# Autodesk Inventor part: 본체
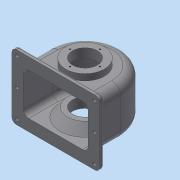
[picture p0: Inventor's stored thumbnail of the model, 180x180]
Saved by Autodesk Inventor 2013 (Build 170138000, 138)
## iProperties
Created: 2015-09
Part Number: 본체
Material: 일반
Document SubType Name: Modeling
Designer: Administrator
Density: 1 g/cm^3
Author: Administrator
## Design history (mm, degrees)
sketch "스케치1"
  geometry: L1 (0, 0)-(0, -47); L2 (0, -47)-(0, 57); L3 (0, -47)-(57, -47); L4 (57, -47)-(57, 0); L5 (0, -47)-(-57, -47); L6 (-57, -47)-(-57, 0); A1 r 57 centre (0, 0) between (57, 0) and (-57, 0)
  constraints: 12 end point, 3 point on circle, 2 perpendicular, 2 tangent, 1 centre point, 1 coincident, 1 collinear, 1 vertical
  dimensions: "d0" = 47 distance of L1.start L1.end; "d1" = 104 distance of L1.end L2.end
extrude "돌출1" new body sketch "스케치1" stored distance "d2" = 77; taper "d3" = 0 deg
fillet "모깎기1" dims "d4" = 14
feature "쉘2" dims "d16" = 5
sketch "스케치5"
  geometry: C1 r 31 at (0, 0); A1 r 43 centre (0, 0) between (43, 0) and (-43, 0) reference
  constraints: 1 centre point, 1 coincident
  dimensions: "d17" = 62 diameter of C1
extrude "돌출4" join sketch "스케치5" distance "d18" = 10; taper "d19" = 0 deg
sketch "스케치6"
  geometry: C1 r 31 at (0, 0) reference; C2 r 20 at (0, 0)
  constraints: 1 centre point, 1 coincident
  dimensions: "d20" = 40 diameter of C2
extrude "돌출5" cut sketch "스케치6" stored distance "d21" = 10; taper "d22" = 0 deg
sketch "스케치7"
  geometry: L1 (-31, 38.5)-(-31, 48.5) reference; L2 (-31, 48.5)-(-20, 48.5) reference; L3 (-20, 48.5)-(-20, 33.5) reference; L4 (-20, 33.5)-(-47, 33.5) reference; L5 (-47, 33.5)-(-47, 38.5) reference; L6 (-47, 38.5)-(-31, 38.5) reference; L7 (57, 24.5)-(57, -24.5) reference; L8 (43, -38.5)-(-47, -38.5) reference; L9 (-47, -38.5)-(-47, -33.5) reference; L10 (-47, -33.5)-(43, -33.5) reference; L11 (52, -24.5)-(52, 24.5) reference; L12 (43, 33.5)-(20, 33.5) reference; L13 (20, 33.5)-(20, 48.5) reference; L14 (20, 48.5)-(31, 48.5) reference; L15 (31, 48.5)-(31, 38.5) reference; L16 (31, 38.5)-(43, 38.5) reference; L17 (0, -19.5)-(28, -19.5); L18 (0, -33.5)-(39.747, -33.5); L19 (28, -19.5)-(39.747, -33.5); L20 (0, -33.5)-(0, -19.5); A1 r 14 centre (43, 24.5) between (57, 24.5) and (43, 38.5) reference; A2 r 14 centre (43, -24.5) between (43, -38.5) and (57, -24.5) reference; A3 r 9 centre (43, -24.5) between (43, -33.5) and (52, -24.5) reference; A4 r 9 centre (43, 24.5) between (52, 24.5) and (43, 33.5) reference; 1 further point
  constraints: 8 end point, 2 point on line, 1 perpendicular
  dimensions: "d24" = 28 distance of L17.start L17.end
revolve "회전1" sketch "스케치7" stored, may be unused: angle "d26" = 90 deg
sketch "스케치8"
  geometry: L1 (-31, 38.5)-(-31, 48.5) reference; L2 (-31, 48.5)-(-20, 48.5) reference; L3 (-20, 48.5)-(-20, 33.5) reference; L4 (-20, 33.5)-(-47, 33.5) reference; L5 (-47, 33.5)-(-47, 38.5) reference; L6 (-47, 38.5)-(-31, 38.5) reference; L7 (57, 24.5)-(57, -24.5) reference; L8 (43, -38.5)-(-47, -38.5) reference; L9 (-47, -38.5)-(-47, -33.5) reference; L10 (-47, -33.5)-(-39.747, -33.5) reference; L11 (-39.747, -33.5)-(-28, -19.5) reference; L12 (-28, -19.5)-(28, -19.5) reference; L13 (28, -19.5)-(39.747, -33.5) reference; L14 (39.747, -33.5)-(43, -33.5) reference; L15 (52, -24.5)-(52, 24.5) reference; L16 (43, 33.5)-(20, 33.5) reference; L17 (20, 33.5)-(20, 48.5) reference; L18 (20, 48.5)-(31, 48.5) reference; L19 (31, 48.5)-(31, 38.5) reference; L20 (31, 38.5)-(43, 38.5) reference; L21 (0, -19.5)-(20, -19.5); L22 (20, -19.5)-(20, -35.5); L23 (20, -35.5)-(0, -35.5); L24 (0, -35.5)-(0, -19.5); A1 r 14 centre (43, 24.5) between (57, 24.5) and (43, 38.5) reference; A2 r 14 centre (43, -24.5) between (43, -38.5) and (57, -24.5) reference; A3 r 9 centre (43, -24.5) between (43, -33.5) and (52, -24.5) reference; A4 r 9 centre (43, 24.5) between (52, 24.5) and (43, 33.5) reference; 1 further point
  constraints: 8 end point, 2 perpendicular, 1 midpoint, 1 parallel, 1 point on line
  dimensions: "d27" = 20 distance of L21.start L21.end; "d28" = 16 distance of L21.end L22.end
revolve "회전2" sketch "스케치8" stored, may be unused: angle "d29" = 90 deg
sketch "스케치9"
  geometry: L1 (-31, 38.5)-(-31, 48.5) reference; L2 (-31, 48.5)-(-20, 48.5) reference; L3 (-20, 48.5)-(-20, 33.5) reference; L4 (-20, 33.5)-(-47, 33.5) reference; L5 (-47, 33.5)-(-47, 38.5) reference; L6 (-47, 38.5)-(-31, 38.5) reference; L7 (57, 24.5)-(57, -24.5) reference; L8 (43, -38.5)-(-47, -38.5) reference; L9 (-47, -38.5)-(-47, -33.5) reference; L10 (-47, -33.5)-(-39.747, -33.5) reference; L11 (-39.747, -33.5)-(-28, -19.5) reference; L12 (-28, -19.5)-(-20, -19.5) reference; L13 (-20, -19.5)-(-20, -35.5) reference; L14 (-20, -35.5)-(20, -35.5) reference; L15 (20, -35.5)-(20, -19.5) reference; L16 (20, -19.5)-(28, -19.5) reference; L17 (28, -19.5)-(39.747, -33.5) reference; L18 (39.747, -33.5)-(43, -33.5) reference; L19 (52, -24.5)-(52, 24.5) reference; L20 (43, 33.5)-(20, 33.5) reference; L21 (20, 33.5)-(20, 48.5) reference; L22 (20, 48.5)-(31, 48.5) reference; L23 (31, 48.5)-(31, 38.5) reference; L24 (31, 38.5)-(43, 38.5) reference; L25 (0, -35.5)-(33, -35.5); L26 (37.416, -38.5)-(33, -33.237); L27 (37.416, -38.5)-(0, -38.5); L28 (0, -35.5)-(0, -38.5); L29 (33, -35.5)-(33, -33.237); L30 (33, -25.459)-(33, -18.456); A1 r 14 centre (43, 24.5) between (57, 24.5) and (43, 38.5) reference; A2 r 14 centre (43, -24.5) between (43, -38.5) and (57, -24.5) reference; A3 r 9 centre (43, -24.5) between (43, -33.5) and (52, -24.5) reference; A4 r 9 centre (43, 24.5) between (52, 24.5) and (43, 33.5) reference; 1 further point
  constraints: 12 end point, 4 point on line, 3 perpendicular, 1 midpoint, 1 parallel
  dimensions: "d30" = 33 distance of L25.start L25.end; "d31" = 5 distance between parallel lines of L17 L26
revolve "회전3" sketch "스케치9" stored, may be unused: angle "d32" = 90 deg
sketch "스케치10"
  geometry: L1 (-14, 14)-(-14, 63) reference; L2 (86, 0)-(0, 0) reference; L3 (100, 14)-(100, 63) reference; L4 (0, 77)-(86, 77) reference; L5 (-27, 90.5)-(113, 90.5); L6 (113, 90.5)-(113, -13.5); L7 (113, -13.5)-(-27, -13.5); L8 (-27, -13.5)-(-27, 90.5); L9 (-27, 90.5)-(113, -13.5); L10 (113, 90.5)-(-27, -13.5); A1 r 14 centre (0, 63) between (0, 77) and (-14, 63) reference; A2 r 14 centre (0, 14) between (-14, 14) and (0, 0) reference; A3 r 14 centre (86, 14) between (86, 0) and (100, 14) reference; A4 r 14 centre (86, 63) between (100, 63) and (86, 77) reference; 1 further point
  constraints: 12 end point, 2 midpoint, 2 parallel, 1 horizontal, 1 perpendicular
  dimensions: "d33" = 140 distance of L6.end L7.end; "d34" = 104 distance of L5.end L6.end
extrude "돌출6" join sketch "스케치10" distance "d35" = 7; taper "d36" = 0 deg
fillet "모깎기2" dims "d37" = 7
fillet "모깎기3" dims "d38" = 1
fillet "모깎기4" dims "d39" = 3
sketch "스케치11"
  geometry: L1 (105, 5.5)-(-19, -82.5); L2 (-19, 5.5)-(105, -82.5); C1 r 2.5 at (-19, 5.5); C2 r 2.5 at (-19, -82.5); C3 r 2.5 at (105, -82.5); C4 r 2.5 at (105, 5.5); C5 r 2.5 at (105, -38.5); C6 r 2.5 at (-19, -38.5); 1 further point
  constraints: 6 centre point, 4 coincident, 4 end point, 2 midpoint
  dimensions: "d40" = 124 distance of L2.end L1.end; "d41" = 88 distance of L1.end L2.start; "d42" = 5 diameter of C1; "d44" = 5 diameter of C3; "d45" = 5 diameter of C4; "d46" = 5 diameter of C5; "d47" = 5 diameter of C6
extrude "돌출7" cut sketch "스케치11" stored distance "d48" = 5 (= d45); taper "d49" = 0 deg
fillet "모깎기5" dims "d50" = 3
sketch "스케치12"
  geometry: L1 (70, -43)-(70, -47) reference; L2 (70, -47)-(64.5, -47) reference; L3 (64.5, -47)-(64.5, -40) reference; L4 (64.5, -40)-(67, -40) reference; L5 (-67, -40)-(-64.5, -40) reference; L6 (-64.5, -40)-(-64.5, -47) reference; L7 (-64.5, -47)-(-70, -47) reference; L8 (-70, -47)-(-70, -43) reference; L9 (-52, 0)-(-52, -47) reference; L10 (-52, -47)-(-59.5, -47) reference; L11 (-59.5, -47)-(-59.5, -40) reference; L12 (-59.5, -40)-(-58, -40) reference; L13 (-57, -39)-(-57, 0) reference; L14 (57, 0)-(57, -39) reference; L15 (58, -40)-(59.5, -40) reference; L16 (59.5, -40)-(59.5, -47) reference; L17 (59.5, -47)-(52, -47) reference; L18 (52, -47)-(52, 0) reference; L19 (0, 63)-(6, 63); L20 (6, 63)-(7.137, 56.551); L21 (0, -47)-(0, 52); L22 (0, 57)-(0, 63); L23 (7.137, 56.551)-(0, 56.551); L24 (0, 56.551)-(0, 57); A1 r 3 centre (67, -43) between (70, -43) and (67, -40) reference; A2 r 3 centre (-67, -43) between (-67, -40) and (-70, -43) reference; A3 r 1 centre (-58, -39) between (-58, -40) and (-57, -39) reference; A4 r 57 centre (0, 0) between (57, 0) and (-57, 0) reference; A5 r 1 centre (58, -39) between (57, -39) and (58, -40) reference; A6 r 52 centre (0, 0) between (52, 0) and (-52, 0) reference; 1 further point
  constraints: 12 end point, 3 perpendicular, 3 point on circle, 2 parallel, 1 collinear
  dimensions: "d51" = 110 distance of L21.start L19.start; "d52" = 6 distance of L19.start L19.end; "d53" = 80 deg angle of L19 L20
revolve "회전4" sketch "스케치12" stored, may be unused: angle "d54" = 90 deg
fillet "모깎기6" dims "d55" = 3
sketch "스케치13"
  geometry: C1 r 6 at (0, 0) reference; 1 further point
  constraints: 1 coincident
hole "구멍1" sketch "스케치13" at (0, 0) diameter "d56" = 4.459; stored, may be unused: countersink angle "d60" = 90 deg, drill point angle "d62" = 118 deg; dims "d57" = 6, "d58" = 4, "d59" = 2, "d61" = 8
sketch "스케치14"
  geometry: C1 r 20 at (0, 0) reference; 1 further point
  dimensions: "d63" = 24 distance of C1.centre point (0, 24)
hole "구멍2" sketch "스케치14" at (0, 24) diameter "d64" = 2.459; stored, may be unused: countersink angle "d68" = 90 deg, drill point angle "d70" = 118 deg; dims "d65" = 6, "d66" = 4, "d67" = 2, "d69" = 8
sketch "스케치15"
  geometry: C1 r 20 at (0, 0) reference; 1 further point
  dimensions: "d74" = 28 distance of C1.centre point (0, 28)
hole "구멍3" sketch "스케치15" at (0, 28) diameter "d75" = 2.459; stored, may be unused: countersink angle "d79" = 90 deg, drill point angle "d81" = 118 deg; dims "d76" = 7, "d77" = 4, "d78" = 2, "d80" = 9
fillet "모깎기7" dims "d85" = 0.5
node "솔리드1"
pattern_circular "원형 패턴1" dims angle "d72" = 360 deg
pattern_circular "원형 패턴2" dims angle "d83" = 360 deg
node "절단 모서리 투영2"
node "절단 모서리 투영3"
node "절단 모서리 투영4"
node "절단 모서리 투영5"
